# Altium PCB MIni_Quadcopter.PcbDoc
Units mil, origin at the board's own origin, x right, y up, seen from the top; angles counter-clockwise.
Board outline 2923.08 x 2923.08 mil, 2 copper layers (Top Layer, Bottom Layer); 50 components, 35 nets, 225 pads, 82 vias.
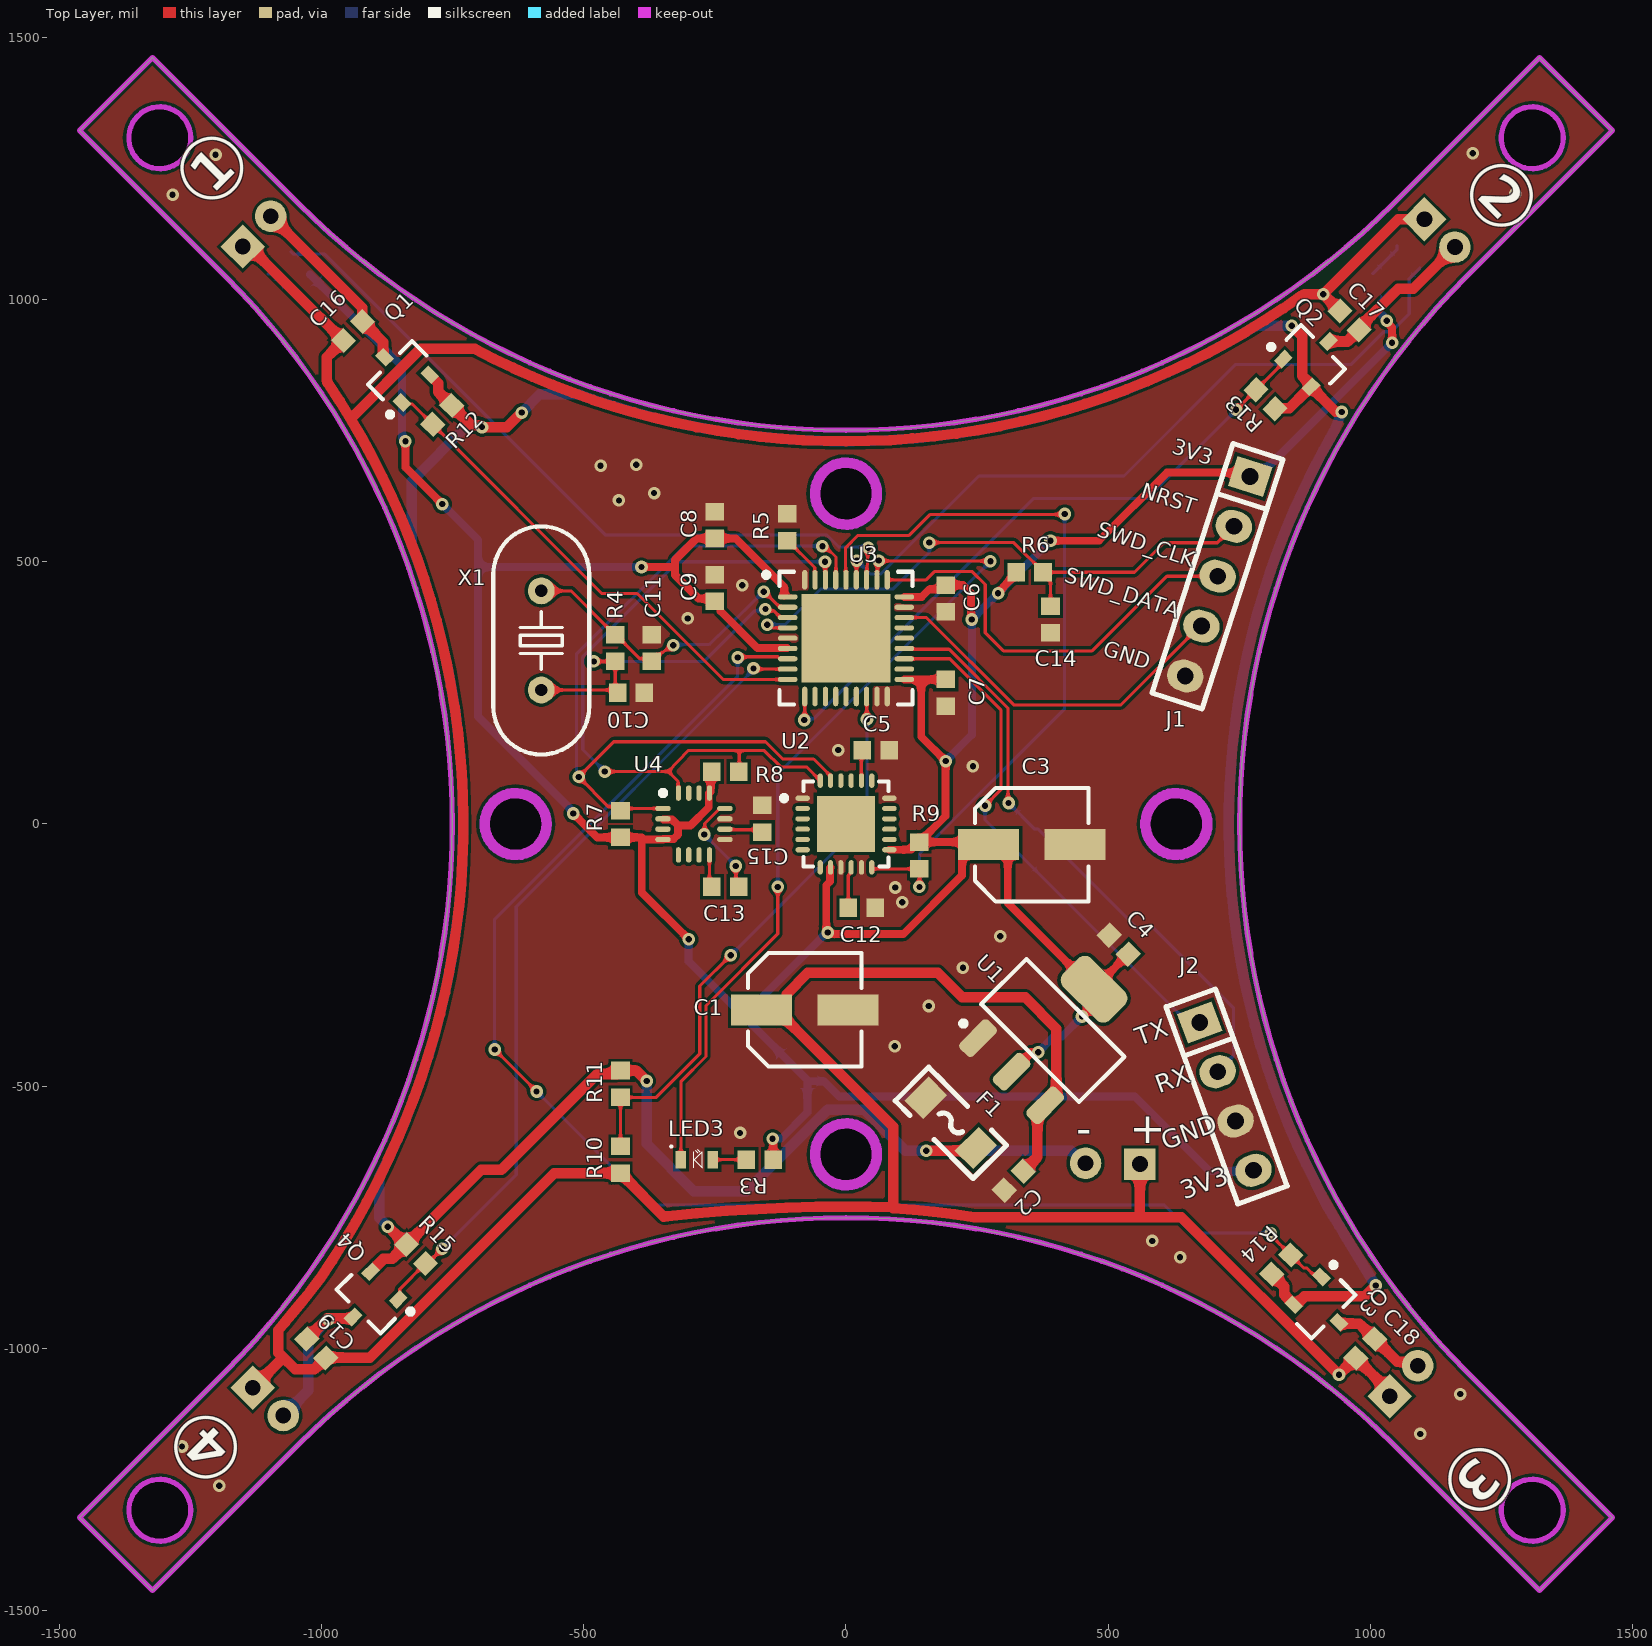
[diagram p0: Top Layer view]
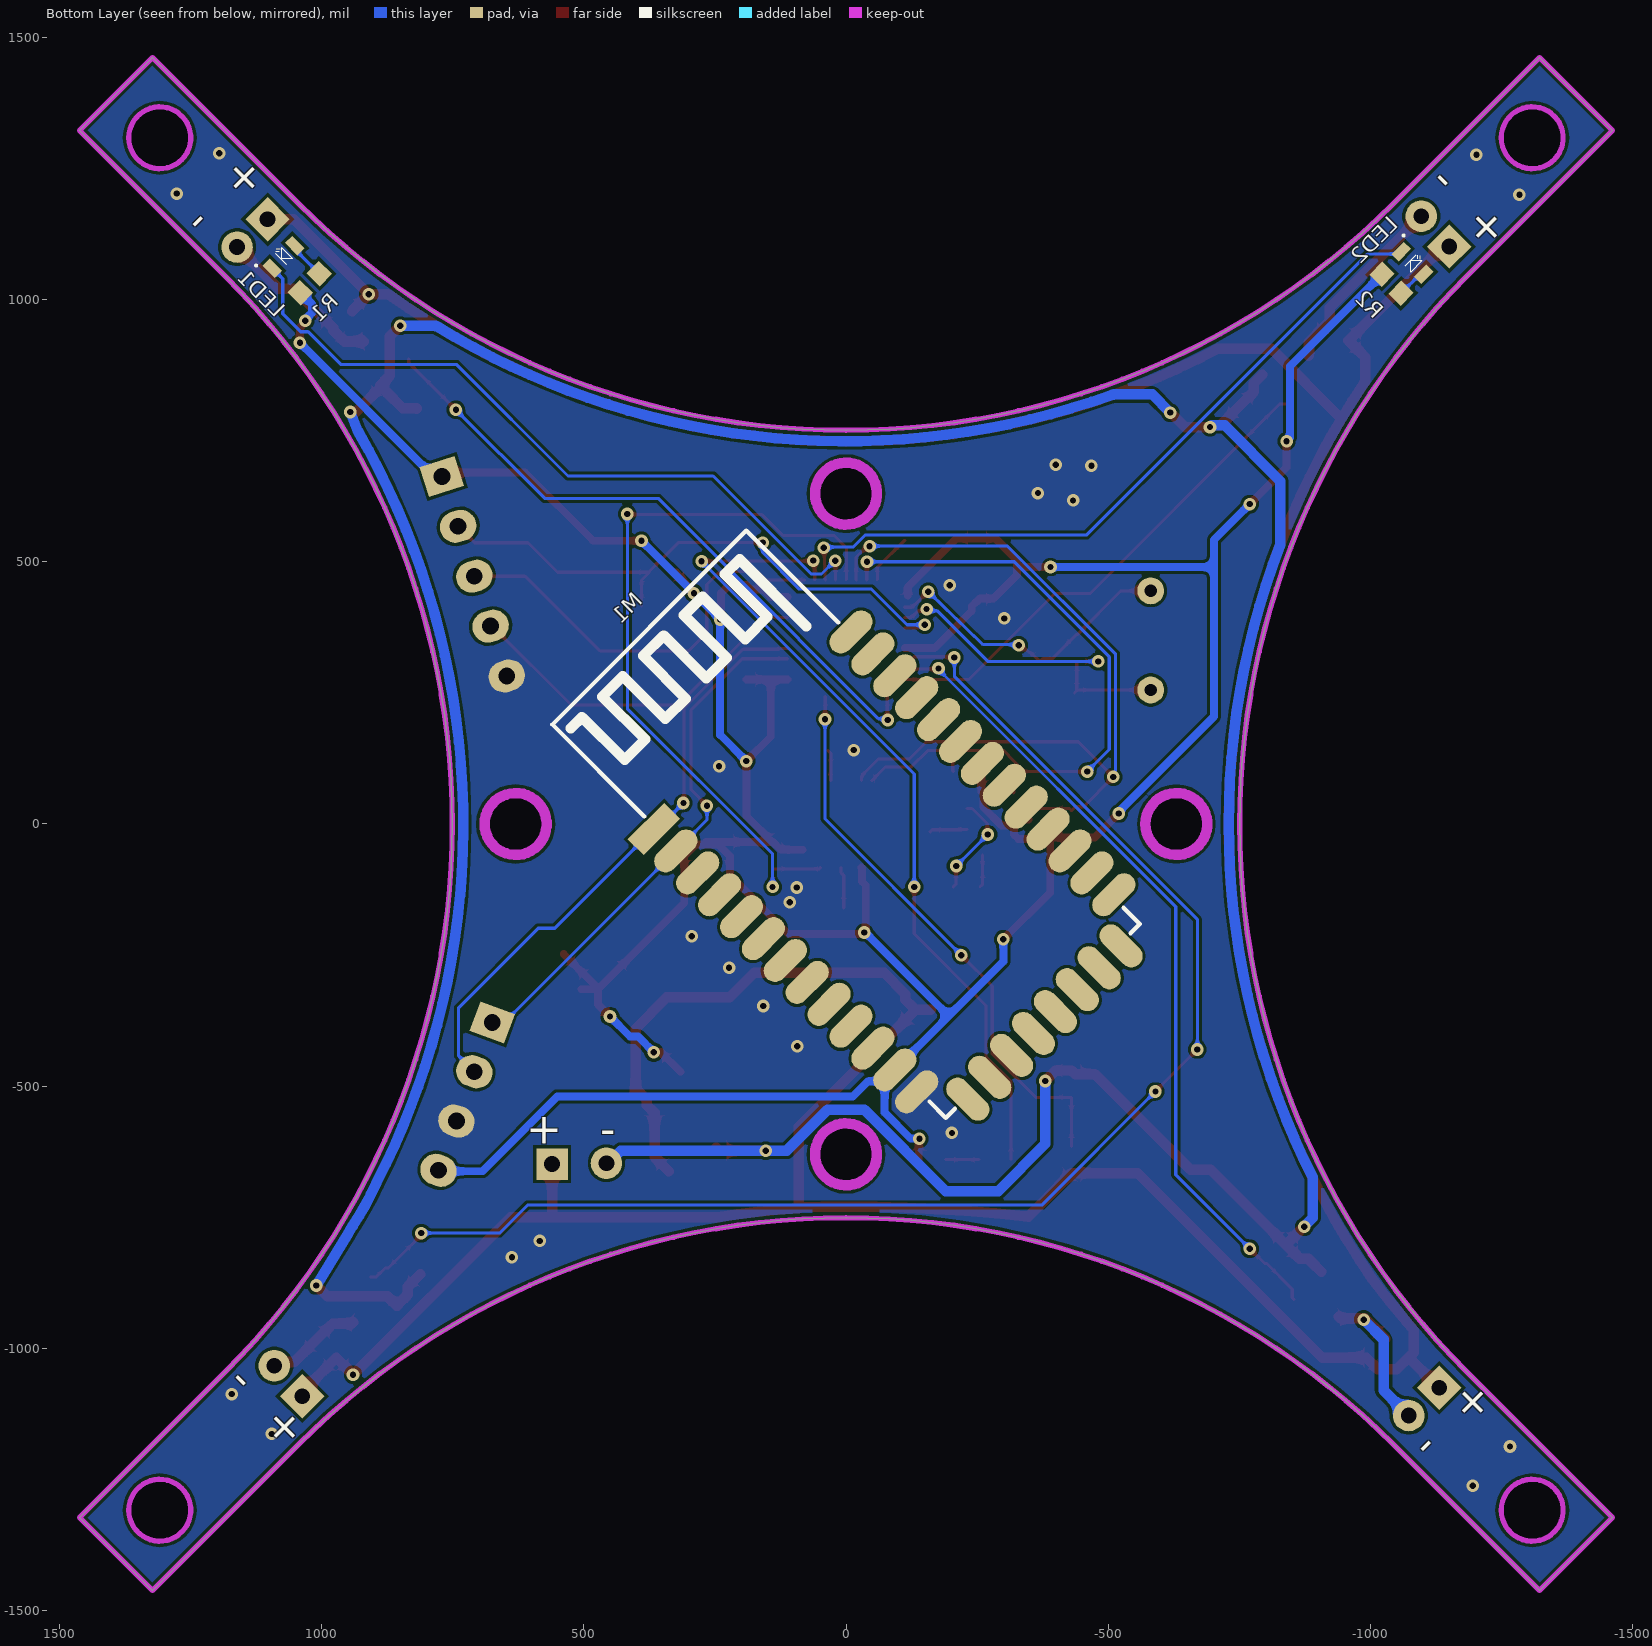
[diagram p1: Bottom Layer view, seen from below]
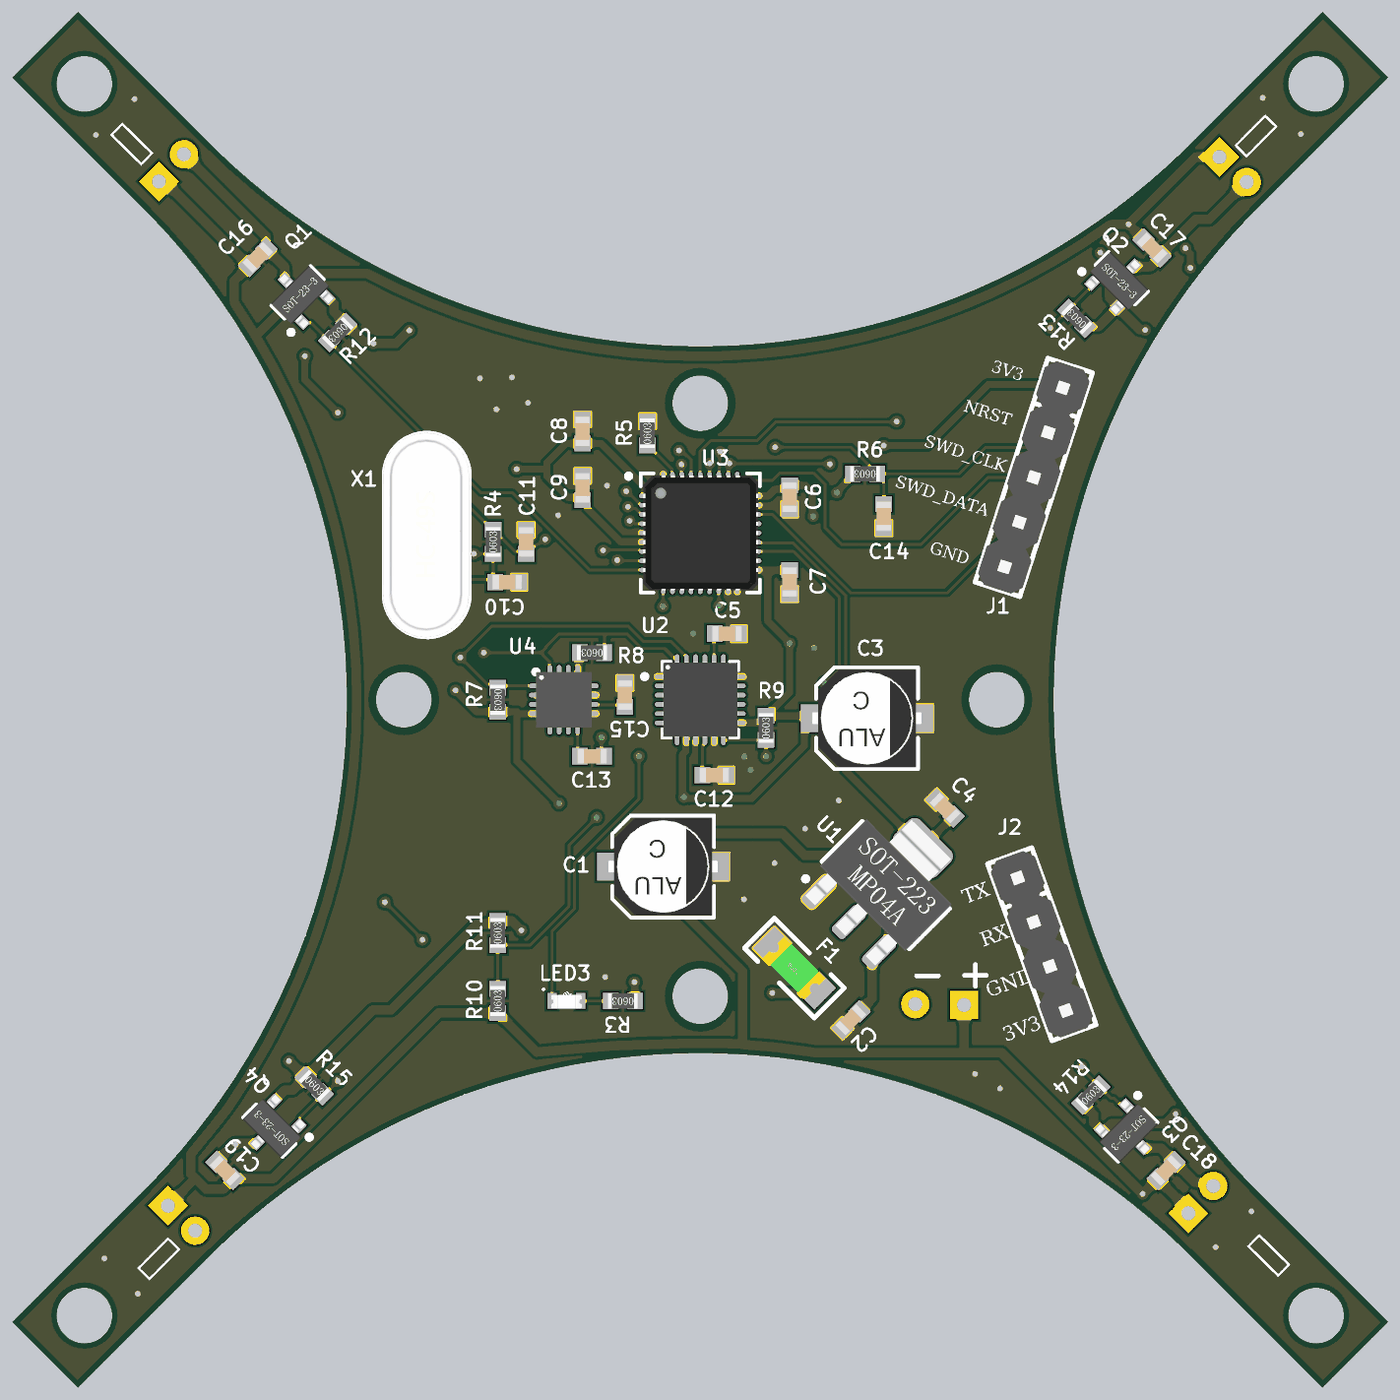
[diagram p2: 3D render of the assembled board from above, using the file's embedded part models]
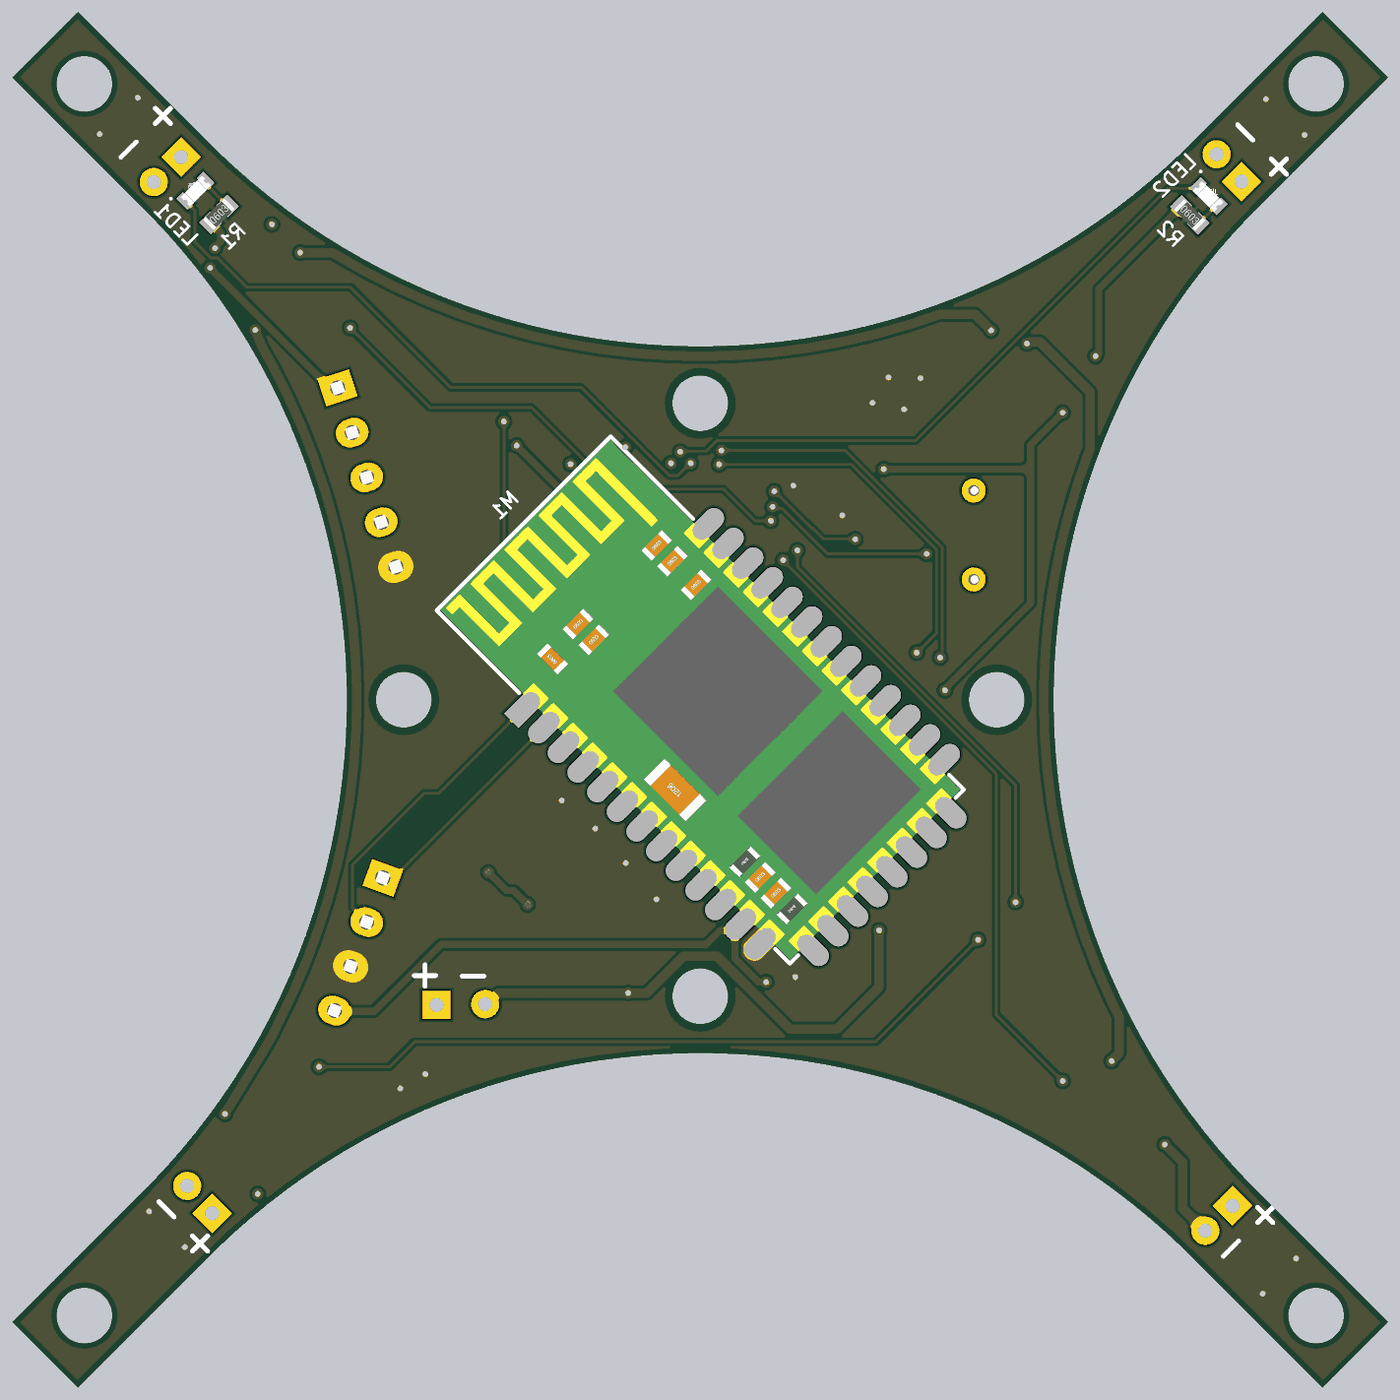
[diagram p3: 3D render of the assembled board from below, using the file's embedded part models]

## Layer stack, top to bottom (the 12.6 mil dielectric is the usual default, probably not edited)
Top Solder: solder mask 0.4, Solder Resist, Dk 3.5
Top Layer: signal copper 1.4
Dielectric 1: dielectric 12.6, FR-4, Dk 4.8
Bottom Layer: signal copper 1.4
Bottom Solder: solder mask 0.4, Solder Resist, Dk 3.5

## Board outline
-1461.54,-1322.35 -1322.35,-1461.54 -1043.96,-1183.15 cw(c0,-2227.11) 1043.96,-1183.15 1322.35,-1461.54 1461.54,-1322.35 1183.15,-1043.96 cw(c2227.11,0) 1183.15,1043.96 1461.54,1322.35 1322.35,1461.54 1043.96,1183.15 cw(c0,2227.11) -1043.96,1183.15 -1322.35,1461.54 -1461.54,1322.35 -1183.15,1043.96 cw(c-2227.11,0) -1183.15,-1043.96
cut-out: -1367.48,-1308.43 ccw(c-1308.43,-1308.43) -1308.43,-1367.48 ccw(c-1308.43,-1308.43) -1249.37,-1308.43 ccw(c-1308.43,-1308.43) -1308.43,-1249.37 ccw(c-1308.43,-1308.43)
cut-out: -59.06,-629.92 ccw(c0,-629.92) 0,-688.98 ccw(c0,-629.92) 59.06,-629.92 ccw(c0,-629.92) 0,-570.87 ccw(c0,-629.92)
cut-out: -688.98,0 ccw(c-629.92,0) -629.92,-59.06 ccw(c-629.92,0) -570.87,0 ccw(c-629.92,0) -629.92,59.06 ccw(c-629.92,0)
cut-out: 1249.37,-1308.43 ccw(c1308.43,-1308.43) 1308.43,-1367.48 ccw(c1308.43,-1308.43) 1367.48,-1308.43 ccw(c1308.43,-1308.43) 1308.43,-1249.37 ccw(c1308.43,-1308.43)
cut-out: 570.87,0 ccw(c629.92,0) 629.92,-59.06 ccw(c629.92,0) 688.98,0 ccw(c629.92,0) 629.92,59.06 ccw(c629.92,0)
cut-out: -59.06,629.92 ccw(c0,629.92) 0,570.87 ccw(c0,629.92) 59.06,629.92 ccw(c0,629.92) 0,688.98 ccw(c0,629.92)
cut-out: -1308.43,1249.37 cw(c-1308.43,1308.43) -1367.48,1308.43 cw(c-1308.43,1308.43) -1308.43,1367.48 cw(c-1308.43,1308.43) -1249.37,1308.43 cw(c-1308.43,1308.43)
cut-out: 1249.37,1308.43 ccw(c1308.43,1308.43) 1308.43,1249.37 ccw(c1308.43,1308.43) 1367.48,1308.43 ccw(c1308.43,1308.43) 1308.43,1367.48 ccw(c1308.43,1308.43)

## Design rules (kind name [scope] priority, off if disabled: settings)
Clearance [All] p1: gap=6 ignorepadtopadclearanceinfootprint=TRUE
PolygonConnect [All] p1: connectstyle=Direct reliefconductorwidth=10 reliefentries=4 polygonreliefangle="90 Angle" airgapwidth=10
RoutingVias [All] p1: holewidth=12 width=24 viastyle="Through Hole" minholewidth=12 minwidth=24 maxholewidth=12 maxwidth=24
SilkToSilkClearance [All] p1: silktosilkclearance=2
SilkToSolderMaskClearance [IsPad] p1: minsilkscreentomaskgap=2 clearancetoexposedcopper=TRUE
SolderMaskExpansion [All] p1: expansion=2.5 istentingtop=FALSE
Width MOTOR [InNetClass('MOTOR')] p1: maxlimit=60 minlimit=8 preferedwidth=20
Width PWR [InNetClass('PWR')] p2: maxlimit=60 minlimit=8 preferedwidth=15
Width [All] p3: maxlimit=6 minlimit=6 preferedwidth=6
28 further rules are at their usual default settings.

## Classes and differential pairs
net class MOTOR: MGND NetC16_1 NetC17_1 NetC18_1 NetC19_1 VCC
net class PWR: 3V3 GND

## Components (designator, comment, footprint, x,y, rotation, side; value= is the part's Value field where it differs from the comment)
C1 "47uF" Cap_SMD_5*5.4mm -78.74,-354.33 r0 top
C2 "0.1uF" C0603 320,-680 r45 top
C3 "47uF" Cap_SMD_5*5.4mm 354.33,-39.37 r0 top
C4 "0.1uF" C0603 520,-230 r315 top
C5 "2.2nF" C0603 56.64,140.46 r0 top
C6 "0.1uF" C0603 190,430 r90 top
C7 "0.1uF" C0603 190,250 r90 top
C8 "0.1uF" C0603 -250,570 r270 top
C9 "0.1uF" C0603 -250,450 r270 top
C10 "22P" C0603 -410,250 r0 top
C11 "22P" C0603 -370,335.59 r90 top
C12 "0.1uF" C0603 30,-160 r0 top
C13 "0.22uF" C0603 -230,-120 r0 top
C14 "1uF" C0603 390,390 r90 top
C15 "4.7uF" C0603 -160,10 r270 top
C16 "0.1uF" C0603 -940,940 r225 top
C17 "0.1uF" C0603 960,960 r135 top
C18 "0.1uF" C0603 990,-1000 r225 top
C19 "0.1uF" C0603 -1010,-1000 r315 top
F1 "MSMD200-8V 2A" "FU 1206" 200,-570 r135 top
J1 "Pin HDR1X5" "Pin HDR1X5/2.54mm-S" 770.46,662.65 r342 top
J2 "Pin HDR1X4" "Pin HDR1X4/2.54mm-S" 674.46,-378.47 r20 top
LED1 "LED" LED_0603 1072.48,1081.36 r135 bottom
LED2 "LED" LED_0603 -1080,1070 r225 bottom
LED3 "LED" LED_0603 -284.41,-640 r0 top
M1 "HC-05" HC-05 0.16,0 r135 bottom
Q1 "SI2302" SOT_23 -850,860 r135 top
Q2 "SI2302" SOT_23 890,890 r45 top
Q3 "SI2302" SOT_23 910,-920 r315 top
Q4 "SI2302" SOT_23 -910,-910 r225 top
R1 "470R" R0603 1022.48,1031.36 r135 bottom
R2 "470R" R0603 -1040,1030 r225 bottom
R3 "470R" R0603 -164.41,-640 r180 top
R4 "1M" R0603 -440,335.59 r90 top
R5 "470R" R0603 -112,566 r90 top
R6 "4.7K" R0603 350,480 r180 top
R7 "4.7K" R0603 -430,0 r270 top
R8 "4.7K" R0603 -230,100 r180 top
R9 "10K" R0603 140,-60 r90 top
R10 "10K" R0603 -430,-640 r90 top
R11 "10K" R0603 -430,-495.59 r90 top
R12 "10K" R0603 -770,780 r225 top
R13 "10K" R0603 800,810 r135 top
R14 "10K" R0603 830,-840 r45 top
R15 "10K" R0603 -820,-820 r315 top
U1 "AMS1117" SOT_223 394.33,-393.7 r45 top
U2 "MPU6050" QFN-24 0,0 r0 top
U3 "STM32F103T8U6" VFQFPN36_L 0,354.33 r0 top
U4 "HMC5883" LPCC-16-50P250X250X90-16N -290,0 r0 top
X1 "8MHZ" "OSC HC-49S" -581,350 r90 top

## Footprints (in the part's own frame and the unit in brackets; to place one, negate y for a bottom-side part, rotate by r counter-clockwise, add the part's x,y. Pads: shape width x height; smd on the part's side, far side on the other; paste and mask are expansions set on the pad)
C0603 [mm]
  rect 0.85x0.9 smd: 1(-0.65,0) 2(0.65,0)
  body extent -0.8,-0.4 0.8,0.4, height 0.8
Cap_SMD_5*5.4mm [mm]
  rect 2.95x1.5 smd: 1(-2.1,0) 2(2.1,0)
  silkscreen extent -2.75,-2.75 2.75,2.75, body extent -2.95,-2.65 2.95,2.65, height 5.41
"FU 1206" [mil] "贴片保险丝"
  rect 50x65 smd: 1(-67.5,0) 2(67.5,0)
  silkscreen extent -105,-45 105,45, body extent -63,-32 63,32, height 34
HC-05 [mm] "串口蓝牙模块"
  rect 2.5x1.1 smd: 1(-6.75,6.403)
  oval 2.5x1.1 smd: 2(-6.75,4.903) 3(-6.75,3.403) 4(-6.75,1.903) 5(-6.75,0.403) 6(-6.75,-1.097) 7(-6.75,-2.597) 8(-6.75,-4.097) 9(-6.75,-5.597) 10(-6.75,-7.097) 11(-6.75,-8.597) 12(-6.75,-10.097) 13(-6.75,-11.597) 22(6.75,-11.597) 23(6.75,-10.097) 24(6.75,-8.597) 25(6.75,-7.097) 26(6.75,-5.597) 27(6.75,-4.097) 28(6.75,-2.597) 29(6.75,-1.097) 30(6.75,0.403) 31(6.75,1.903) 32(6.75,3.403) 33(6.75,4.903) 34(6.75,6.403)
  oval 1.1x2.5 smd: 14(-5.25,-13.597) 15(-3.75,-13.597) 16(-2.25,-13.597) 17(-0.75,-13.597) 18(0.75,-13.597) 19(2.25,-13.597) 20(3.75,-13.597) 21(5.25,-13.597)
  silkscreen extent -6.65,-13.49 6.64,13.46, body extent -6.52,-13.37 6.52,13.35, height 2.46
LED_0603 [mm]
  rect 0.5x0.85 smd: 1(-0.775,0) 2(0.775,0)
  silkscreen extent -1.29,-0.38 0.25,0.69, body extent -0.82,-0.4 0.83,0.32, height 0.68
LPCC-16-50P250X250X90-16N [mm]
  oval 0.75x0.254 smd: 1(-1.5,0.75) 2(-1.5,0.25) 3(-1.5,-0.25) 4(-1.5,-0.75) 9(1.5,-0.75) 10(1.5,-0.25) 11(1.5,0.25) 12(1.5,0.75)
  oval 0.254x0.75 smd: 5(-0.75,-1.5) 6(-0.25,-1.5) 7(0.25,-1.5) 8(0.75,-1.5) 13(0.75,1.5) 14(0.25,1.5) 15(-0.25,1.5) 16(-0.75,1.5)
  silkscreen extent -1.62,1.38 -1.37,1.62, body extent -1.5,-1.5 1.5,1.5, height 0.9
"OSC HC-49S" [mm]
  round 1.3 hole 0.6: 1(-2.4,0) 2(2.4,0)
  silkscreen extent -5.52,-2.32 5.52,2.33, body extent -5.53,-2.29 5.53,2.36, height 4.13
"Pin HDR1X4/2.54mm-S" [mil]
  rect 70x60 hole 32: 1(0,0)
  oval 70x60 hole 32: 2(0,-100) 3(0,-200) 4(0,-300)
  silkscreen extent -50,-350 50,50, body extent -50,-350 50,50, height 336
"Pin HDR1X5/2.54mm-S" [mil]
  rect 70x60 hole 32: 1(0,0)
  oval 70x60 hole 32: 2(0,-100) 3(0,-200) 4(0,-300) 5(0,-400)
  silkscreen extent -50,-450 50,50, body extent -50,-450 50,50, height 336
QFN-24 [mm]
  oval 0.7x0.25 smd: 1(-2.1,1.25) 2(-2.1,0.75) 3(-2.1,0.25) 4(-2.1,-0.25) 5(-2.1,-0.75) 6(-2.1,-1.25) 13(2.1,-1.25) 14(2.1,-0.75) 15(2.1,-0.25) 16(2.1,0.25) 17(2.1,0.75) 18(2.1,1.25)
  oval 0.25x0.7 smd: 7(-1.25,-2.1) 8(-0.75,-2.1) 9(-0.25,-2.1) 10(0.25,-2.1) 11(0.75,-2.1) 12(1.25,-2.1) 19(1.25,2.1) 20(0.75,2.1) 21(0.25,2.1) 22(-0.25,2.1) 23(-0.75,2.1) 24(-1.25,2.1)
  rect 2.8x2.7 smd: ""(0,0)
  silkscreen extent -3.12,-2.05 2.05,2.05, body extent -2.02,-2.02 2.02,2.02, height 0.95
R0603 [mm]
  rect 0.85x0.9 smd: 1(-0.65,0) 2(0.65,0)
  body extent -0.8,-0.4 0.8,0.4, height 0.45
SOT_23 [mm]
  rect 0.75x0.55 smd: 1(-1.075,0.95) 2(-1.075,-0.95) 3(1.075,0)
  silkscreen extent -1.2,-1.5 0.7,1.9, body extent -1.4,-1.45 1.4,1.45, height 1.2
SOT_223 [mm] "SOT223, 4-Leads, Body 6.50x7.00mm (avg), Pitch 2.30mm, IPC High Density"
  rrect50% 1.95x0.9 smd: 1(-2.825,2.3) 2(-2.825,0) 3(-2.825,-2.3)
  rrect50% 1.95x3.2 smd: 4(2.825,0)
  silkscreen extent -2.95,-3.35 1.55,3.42, body extent -3.48,-3.25 3.48,3.25, height 1.7
VFQFPN36_L [mm] "QFN, 36-Leads, Body 6x6mm, Pitch 0.5mm, Thermal Pad 4.3x4.3mm, IPC High Density"
  oval 0.95x0.25 smd: 1(-2.825,2) 2(-2.825,1.5) 3(-2.825,1) 4(-2.825,0.5) 5(-2.825,0) 6(-2.825,-0.5) 7(-2.825,-1) 8(-2.825,-1.5) 9(-2.825,-2) 19(2.825,-2) 20(2.825,-1.5) 21(2.825,-1) 22(2.825,-0.5) 23(2.825,0) 24(2.825,0.5) 25(2.825,1) 26(2.825,1.5) 27(2.825,2)
  oval 0.25x0.95 smd: 10(-2,-2.825) 11(-1.5,-2.825) 12(-1,-2.825) 13(-0.5,-2.825) 14(0,-2.825) 15(0.5,-2.825) 16(1,-2.825) 17(1.5,-2.825) 18(2,-2.825) 28(2,2.825) 29(1.5,2.825) 30(1,2.825) 31(0.5,2.825) 32(0,2.825) 33(-0.5,2.825) 34(-1,2.825) 35(-1.5,2.825) 36(-2,2.825)
  rect 4.3x4.3 smd: 37(0,0)
  silkscreen extent -3.99,-3.21 3.22,3.21, body extent -3.08,-3.1 3.13,3.1, height 0.9

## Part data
C1 C3: library part Cap2, "极性电容"
C2 C4 C5 C6 C7 C8 C9 C10 C11 C12 C13 C14 C15 C16 C17 C18 C19: library part Cap1, "无极电容"
F1: library part FU, "贴片保险丝"
LED1 LED2 LED3: "发光二极管"
M1: "串口蓝牙模块"
Q1 Q2 Q3 Q4: "N沟道 20V/3A"
R1 R2 R3 R4 R5 R6 R7 R8 R9 R10 R11 R12 R13 R14 R15: library part Res, "普通电阻"
U1: "稳压电源芯片降压IC"
U2: "六轴传感器"
U4: "地磁传感器"
X1: library part XTAL-2P, "2脚无源脚晶振"

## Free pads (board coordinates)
  rect 60x60 hole 30 rot 135: 2(-1150,1101) 2(1037,-1091)
  rect 60x60 hole 30 rot 45: 2(-1131,-1075) 2(1103,1153)
  rect 60x60 hole 30: 2(560.49,-648.46)
  round 60 hole 30: 2(1161,1100) 3(-1097,1159) 3(-1073,-1128) 3(456.78,-646.77) 3(1090,-1033)

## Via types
v1: diameter 24, hole 12, Top Layer to Bottom Layer, tented both sides, 82 vias

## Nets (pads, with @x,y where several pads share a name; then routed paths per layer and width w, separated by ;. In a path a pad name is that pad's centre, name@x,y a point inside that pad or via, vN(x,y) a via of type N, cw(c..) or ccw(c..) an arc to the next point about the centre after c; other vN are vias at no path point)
3V3: C3.1 C4.2 C6.2 C7.2 C8.2 C9.2 J1.1 J2.4 M1.12 R1.1 R2.1 R3.1 R6.2 R7.2 R8.2 R9.2 U1.2 U1.4 U2.8 U2.13 U3.1 U3.6 U3.19 U3.27 U4.2 U4.4 U4.13 | length 8107.3
  Top Layer w15: v1(-840,730) -840,680 v1(-770,610) ; v1(-520,20) -474.41,-25.59 R7.2 -389.43,-25.59 ; v1(-390,490) -329.39,490 ; U4.4 -385.49,-29.53 -389.43,-25.59 ; U4.4@-347.87,-28.34 -328.34,-28.34 -320,-20 -320,-2.97 ; U4.2@-347.87,8.66 -331.63,8.66 -320,-2.97 ; v1(-300,-220) -389.43,-130.57 -389.43,-25.59 ; U4.13@-261.66,57.87 -261.66,32.03 -296.66,-2.97 -320,-2.97 ; U4.13 -258.03,61.5 -258.03,97.56 R8.2 ; v1(-140,-600) cw(c-142.85,-602.85) -138.82,-602.85 R3.1 ; U3.1@-117.77,435.65 -117.77,451.86 -210.32,544.41 C8.2 -284.98,544.41 -326.1,503.28 -326.1,474.89 -281.22,430 -255.59,430 C9.2 -249.02,424.41 -239.78,415.18 -239.78,406.4 -169.09,335.71 U3.6@-112.29,335.71 ; U2.8 -30.79,-83.94 -30.79,-109.96 -37.65,-116.81 -37.65,-203.85 v1(-34.57,-206.92) -31.49,-210 109.07,-210 221.08,-97.99 221.08,-61.4 243.11,-39.37 C3.1 ; U2.13 124.21,-49.21 139.02,-34.41 R9.2 R9.2@140.98,-34.41 ; U3.19 143.42,275.59 ; U3.27 144.46,433.07 158.78,447.4 181.8,447.4 C6.2 222.83,455.59 238.28,440.14 238.28,391.72 v1(240,390) ; C7.2 143.42,275.59 ; v1(290,440) 324.41,479.02 R6.2 ; U1.2 353.03,-435 v1(366.5,-435) ; v1(390,540) 482.07,540.04 612.03,670 763.12,670 J1.1 ; v1(450,-367) 472.98,-344.02 U1.4 ; U1.4@504.55,-315.06 U1.4 ; C4.2 472.98,-313.21 U1.4 ; J2.4@775.31,-658.63 J2.4 ; v1(1031.01,959.47) 1031.01,957.03 1041.24,946.8 v1(1041.24,917.52) ; R9.2@140.98,-34.41 266.69,-34.41 C3.1 ; R9.2@140.98,-34.41 150.22,-25.18 150.22,-24.19 190,15.59 v1(190,120) 143.42,166.58 143.42,275.59 ; C3.1 286.5,-39.37 308.53,-61.4 308.53,-150.61 U1.4
  Bottom Layer w15: R2.1 -846.52,872.71 -846.52,736.52 v1(-840,730) ; v1(-770,610) -701.77,541.77 -701.77,490 ; v1(-520,20) -520,22.44 -524.5,26.94 -524.5,27.68 -701.77,204.96 -701.77,490 ; v1(-390,490) -701.77,490 ; v1(-300,-220) -300,-262.02 -196.01,-366.01 ; v1(-140,-600) -123.6,-600 -73.69,-550.09 M1.12@-73.69,-488.49 ; v1(-34.57,-206.92) -36.92,-206.92 -196.01,-366.01 ; v1(190,120) 240,170 v1(240,390) v1(290,440) v1(390,540) ; v1(366.5,-435) 396.57,-404.93 412.07,-404.93 v1(450,-367) ; J1.1 786.37,662.65 v1(1041.24,917.52) ; J2.4 775.36,-662.09 693.02,-662.09 550.64,-519.72 -12.76,-519.72 -42.07,-490.41 -71.62,-490.41 M1.12 -196.01,-366.01 ; v1(1031.01,959.47) 1031.01,961.9 1018.5,974.41 1018.5,991.2 R1.1
GND: C1.2 C2.1 C3.2 C4.1 C5.2 C6.1 C7.1 C8.1 C9.1 C10.2 C11.2 C12.2 C14.1 C15.1 F1.2 J1.5 J2.3 M1.13 R5.2 U1.1 U2.1 U2.9 U2.11 U2.18 U3.5 U3.17 U3.18 U3.26 U3.36 U4.9 U4.11
  other v1: -1195,-1262 -1266,-1187 1095,-1163 1171,-1087 637,-826 584,-795 -202,-589 93,-424 158,-347 223,-274 294,-214 107,-149 94,-121 242,110 -15,141 -302,392 -198,455 -433,617 -366,631 -468,683 -400,685 -1284,1200 1276,1202 -1202,1276 1195,1279
INT_SENSOR: R9.1 U2.12 U3.32 | length 1459.3
  Top Layer w6: U3.32 -0.74,466.29 -0.74,526.73 22.97,550.43 120.43,550.43 160,590 416.1,590 v1(417.27,591.17) ; U2.12 49.21,-83.82 50.99,-85.59 R9.1 v1(140,-120)
  Bottom Layer w6: v1(140,-120) 140,-57.08 416.83,219.75 416.83,590.73 v1(417.27,591.17)
LED1: LED1.1 U3.31 | length 1402.1
  Top Layer w6: U3.31 19.97,465.84 19.97,501.92 v1(20.26,502.21)
  Bottom Layer w6: v1(20.26,502.21) 21.14,502.21 46.72,476.63 66.33,476.63 253.26,663.57 530.11,663.57 742.84,876.3 963.47,876.3 1025.64,938.47 1039.71,938.47 1073.93,972.7 1073.93,1039.67 LED1.1
LED2: LED2.1 U3.30 | length 1397.9
  Top Layer w6: U3.30 39.37,466.06 39.88,466.06 39.93,466.21 40.11,466.67 40.2,466.91 40.32,467.24 40.11,467.45 40.11,492.35 41.26,493.51 41.26,525.6 v1(42.54,526.88)
  Bottom Layer w6: LED2.1 -1053.55,1086.7 -994.22,1086.7 -458.41,550.9 -36.27,550.9 -13.39,528.03 41.39,528.03 v1(42.54,526.88)
LED3: LED3.1 U3.29 | length 1638.7
  Top Layer w6: LED3.1 -314.92,-491.23 -266.97,-443.28 -266.97,-346.54 -130,-209.58 v1(-130,-120) ; U3.29 59.53,466.02 59.53,477.94 59.79,478.21 59.79,499.79 v1(62.26,502.26) ; v1@61.08,500 62.63,501.54 274.69,501.54 v1(275.41,500.82)
  Bottom Layer w6: v1(-130,-120) -130,95.41 v1(275.41,500.82)
MGND: F1.1 pad.3@456.78,-646.77 Q1.2 Q2.2 Q3.2 Q4.2 R11.2 R12.1 R13.1 R14.1 R15.1 | length 7662.6
  Top Layer w20: Q4.2 -882,-829.1 -865.29,-829.1 R15.1 ; v1(-874.01,-767.71) -873.15,-767.71 -838.96,-801.9 R15.1 ; Q1.2 -777.78,840.67 -777.78,823.97 R12.1 -714.57,760.77 -699.06,760.77 -695.08,756.78 -646.87,756.78 -619.17,784.48 v1(-618.09,784.48) ; v1(-380,-490) -400,-470 R11.2 -436.73,-476.73 -474.61,-476.73 -656.9,-659.02 -695.21,-659.02 R15.1 ; v1(153.03,-623.03) 242.43,-623.03 F1.1 ; R14.1 835.75,-881.94 835.75,-897.47 853.63,-915.35 Q3.2 855.28,-918.17 856.44,-918.17 873.95,-900.67 989.33,-900.67 v1(1010,-880) ; R13.1 818.79,792.6 845.49,792.6 Q2.2 933.76,786.38 944.63,786.38 v1(945.4,785.62) ; v1(850,950) 869.65,930.35 869.65,854.7 888.04,836.31 Q2.2@888.04,835.14
  Bottom Layer w20: v1(-874.01,-767.71) -874.01,-766.63 -890,-750.64 -890,-674.01 ccw(c-2227.11,0) -729.73,-0.1 ccw(c-2227.11,0) -828.3,534.3 -828.3,653.52 -721.81,760 -697.22,760 v1(-694,756.78) ; v1(-618.09,784.48) -583.53,819.04 -511.61,819.04 cw(c-511.66,806.04) -507.3,818.28 ccw(c0,2227.11) 492.43,813.02 ccw(c0,2227.11) 778.7,948.13 cw(c785.41,937) 785.36,950 v1(850,950) ; v1(-380,-490) -380,-610 -290,-700 -190.36,-700 -35.23,-544.87 35.23,-544.87 113.4,-623.03 429.17,-623.03 452.9,-646.77 pad.3@456.78,-646.77 ; 790.96,-423.83 ccw(c1707.99,-153.18) 791.17,-424.51 ccw(c2227.11,0) 895.42,-684.65 cw(c883.85,-690.57) 895.67,-685.16 ccw(c1433.42,-440.22) 940.87,-766.67 cw(c930.06,-773.89) 941.17,-767.14 941.8,-768.19 ccw(c2227.11,0) 948.91,-779.96 v1(1010,-880) ; 790.95,-423.78 790.92,-423.67 cw(c2227.11,0) 930.79,749.47 v1(945.4,785.62)
NetC5_1: C5.1 U2.20 | length 59.6
  Top Layer w6: U2.20 29.17,83.04 29.17,134.76 C5.1@34.41,140
NetC10_1: C10.1 R4.1 U3.3 X1.1 | length 662
  Top Layer w6: X1.1 -441.1,255.51 C10.1@-440,254.41 ; v1(-481,310) R4.1 C10.1@-440,254.41 ; C10.1 C10.1@-440,254.41 ; v1(-153.68,409.77) -150.24,406.33 -137.63,406.33 -125,393.7 U3.3
  Bottom Layer w6: v1(-481,310) -270.33,310 -174,406.33 -157.13,406.33 v1(-153.68,409.77)
NetC11_1: C11.1 R4.2 U3.2 X1.2 | length 589.6
  Top Layer w6: X1.2 -524.29,444.49 -440.98,361.18 R4.2 -439.02,361.18 -393.2,315.37 -375.37,315.37 C11.1 -355.28,323.73 v1(-329.15,340.85) ; v1(-157.11,442.89) -155.55,442.89 -126.04,413.39 U3.2
  Bottom Layer w6: v1(-329.15,340.85) -327.99,342.01 -263.46,342.01 -261.03,342.01 -259.28,343.71 v1(-157.11,442.89)
NetC13_1: C13.1 U4.8 | length 63
  Top Layer w6: U4.8 -260.47,-115.12 C13.1
NetC13_2: C13.2 U4.12 | length 198.7
  Top Layer w6: v1(-270,-20) -269.35,-19.35 -269.35,1 -246.51,23.84 -246.22,23.84 -240.54,29.53 U4.12 ; v1(-210,-80) -210,-114.41 C13.2
  Bottom Layer w6: v1(-270,-20) v1(-210,-80)
NetC15_2: C15.2 U4.10 | length 73.3
  Top Layer w6: U4.10 -230.18,-10.61 -217.59,-10.61 -217.36,-10.84 -164.75,-10.84 C15.2
NetC16_1: C16.1 pad.3@-1097,1159 Q1.3 | length 359
  Top Layer w6: Q1.3@-882.71,892.71 Q1.3
  Top Layer w20: pad.3@-1097,1159 -922.6,984.6 -922.6,958.79 C16.1 -882.71,918.9 Q1.3@-882.71,892.71
NetC17_1: C17.1 pad.2@1161,1100 Q2.3 | length 320.5
  Top Layer w20: Q2.3 922.71,922.71 923.88,922.71 926.66,919.93 956.12,919.93 C17.1 978.1,946.15 1052.86,1020.92 1081.92,1020.92 pad.2@1161,1100
NetC18_1: C18.1 pad.3@1090,-1033 Q3.3 | length 184.5
  Top Layer w20: Q3.3 942.71,-952.71 978.9,-952.71 C18.1 1051.54,-1025.35 1082.35,-1025.35 pad.3@1090,-1033
NetC19_1: C19.1 pad.3@-1073,-1128 Q4.3 | length 324.2
  Top Layer w20: C19.1 -988.9,-942.71 -942.71,-942.71 Q4.3
  Bottom Layer w20: pad.3@-1073,-1128 -1024.89,-1079.89 -1024.89,-982.89 v1(-987,-945)
NetLED1_2: LED1.2 R1.2 | length 72.7
  Bottom Layer w6: R1.2 1050.91,1095.98 LED1.2
NetLED2_2: LED2.2 R2.2 | length 58.6
  Bottom Layer w6: LED2.2 -1094.62,1048.42 R2.2
NetLED3_2: LED3.2 R3.2 | length 63.9
  Top Layer w6: LED3.2 R3.2
NetR5_1: R5.1 U3.35 | length 97.4
  Top Layer w6: R5.1 -111.02,540.41 -59.79,489.18 -59.79,466.29 U3.35
NetR10_2: R10.2 R11.1 U3.16 | length 1092.4
  Top Layer w6: R10.2 R11.1 -361.84,-521.18 -278.97,-438.31 -278.97,-308.97 v1(-220,-250) ; U3.16 39.69,242.8 39.69,200.31 v1(40,200)
  Bottom Layer w6: v1(-220,-250) 40,10 v1(40,200)
NRST: C14.2 J1.2 R6.1 U3.4 | length 1137.4
  Top Layer w6: v1(-150,380) -145.13,380 -139.14,374.02 U3.4 ; v1(159,536.58) 319.99,536.58 375.59,480.98 R6.1 ; C14.2 390,464.61 375.59,479.02 R6.1 ; J1.2 708.17,536.15 606.37,536.15 550.21,480 R6.1
  Bottom Layer w6: v1(-150,380) -116.37,380 -48.61,447.76 89.07,447.76 159,517.69 v1(159,536.58)
PWM_DOWM: Q4.1 R15.2 U3.8 | length 1551.7
  Top Layer w6: Q4.1 -850.84,-903.74 -850.84,-887.03 R15.2 -798.1,-838.1 v1(-770,-810) ; v1(-176.45,296.59) -175.08,295.22 -111.28,295.22 U3.8
  Bottom Layer w6: v1(-770,-810) -628.77,-668.77 -628.77,-157.66 -176.45,294.66 v1(-176.45,296.59)
PWM_LEFT: Q3.1 R14.2 U3.7 | length 2795.1
  Top Layer w6: v1(-670,-430) v1(-590,-510) ; v1(-206.29,317.41) -204.93,318.77 -129.85,318.77 -126.04,314.96 U3.7 ; v1(810,-780) 810,-783.81 R14.2 872.77,-846.58 878.4,-846.58 895.45,-863.63 Q3.1
  Bottom Layer w6: v1(-670,-430) -670,-181.92 -206.66,281.42 -206.66,317.04 v1(-206.29,317.41) ; v1(-590,-510) -373.32,-726.68 607.29,-726.68 660.6,-780 v1(810,-780)
PWM_RIGHT: Q1.1 R12.2 U3.9 | length 954
  Top Layer w6: Q1.1 -843.74,800.84 -827.03,800.84 R12.2 -465.8,439.61 -398.22,439.61 -234.2,275.59 U3.9
PWM_UP: Q2.1 R13.2 U3.10 | length 1249
  Top Layer w6: U3.10 -78.68,243.05 -78.68,196.25 v1@-78.61,196.18 ; v1(743.81,790) R13.2 833.63,879.82 Q2.1
  Bottom Layer w6: v1(-79.45,198.38) -76.97,200.86 -61.84,200.86 242,504.7 358.09,620.79 574.6,620.79 v1(743.81,790)
REG: C12.1 U2.10 | length 79.6
  Top Layer w6: C12.1 4.41,-98.01 9.84,-92.58 U2.10
RX: J2.2 M1.1 U3.22 | length 1151.1
  Top Layer w6: U3.22 126.04,334.65 126.78,333.91 128.45,333.91 129.18,333.18 196.56,333.18 308.8,220.94 308.8,41.2 v1(310,40)
  Bottom Layer w6: v1(310,40) 359.66,-9.66 M1.1 555.38,-198.72 586.68,-198.72 739,-351.04 739,-441.22 708.66,-471.56 J2.2
SCL_SENSOR: R7.1 U2.23 U3.33 U4.1 | length 1601.4
  Top Layer w6: U4.1 -426.06,29.53 R7.1 -437.61,33.2 -453.2,33.2 v1(-509.77,89.77) -442.83,156.72 -153.54,156.72 -120.68,123.86 -61.65,123.86 -29.53,91.73 U2.23 ; v1(-45,529.58) -40.13,529.58 -28.14,517.59 -27.59,517.59 -19,509 -19,466.24 U3.33
  Bottom Layer w6: v1(-509.77,89.77) -513.21,93.21 -513.21,101.5 -514,102.29 -514,323.67 -307.67,530 -45.42,530 v1(-45,529.58)
SDA_SENSOR: R8.1 U2.24 U3.34 U4.16 | length 1348.9
  Top Layer w6: v1(-460,100) -338.67,100 ; U4.16 -320.29,59.82 -320.29,81.63 -338.67,100 ; R8.1 -203.51,100.89 -203.51,140 ; U2.24 -75.37,108.84 -124.75,108.84 -155.91,140 -203.51,140 ; v1(-40,500) -39.68,499.68 -39.68,465.87 U3.34 ; -338.67,100 -300.73,140 -203.51,140
  Bottom Layer w6: v1(-460,100) -502,142 -502,318.7 -320.7,500 v1(-40,500)
SWD_CLK: J1.3 U3.28 | length 812
  Top Layer w6: U3.28 80.52,465.55 152.78,465.55 168.56,481.32 240.71,481.32 265.4,456.63 265.4,364.6 300,330 469.29,330 611.73,472.44 J1.3
SWD_DATA: J1.4 U3.25 | length 697.8
  Top Layer w6: U3.25 153.08,393.7 319.69,227.09 524.3,227.09 674.55,377.34 J1.4
TX: J2.1 M1.2 U3.21 | length 1015.9
  Top Layer w6: U3.21 197.81,314.96 295.28,217.49 295.28,64.97 v1(265.15,34.85)
  Bottom Layer w6: v1(265.15,34.85) 265.15,7.84 324.41,-51.42 M1.2 651.62,-378.47 J2.1
VCC: C1.1 C2.2 C16.2 C17.2 C18.2 C19.2 pad.2@560.49,-648.46 pad.2@1037,-1091 pad.2@1103,1153 pad.2@-1131,-1075 pad.2@-1150,1101 R10.1 U1.3 | length 8722.2
  Top Layer w20: pad.2@-1150,1101 -1138.08,1101 -1048.83,1011.75 -958.99,921.9 C16.2 -990,890 -990,847.58 ccw(c-977,847.63) -987.8,840.39 cw(c-2227.11,0) -944.51,772.71 ; pad.2@-1131,-1075 -1074.5,-1018.5 -1074.5,-1015.5 ; C1.1 -132.87,-354.33 89.98,-577.18 89.98,-730.86 ccw(c0,-4302.4) -0.07,-729.73 ccw(c0,-3949.82) -340.93,-747.83 ccw(c0,-3949.82) -347.1,-748.49 -422.28,-673.31 -422.28,-672.32 -429.02,-665.59 R10.1 -556.09,-665.59 -907.9,-1017.4 -991.21,-1017.4 C19.2 -1013.81,-1040 -1050,-1040 -1074.5,-1015.5 ; C1.1@-127.79,-349.25 -113.35,-334.8 -113.35,-324.64 -72.59,-283.89 174.89,-283.89 221.75,-330.75 341.75,-330.75 401.09,-390.09 401.09,-504.09 379.72,-525.46 U1.3 365.1,-550.99 365.1,-634.9 C2.2 ; 89.88,-732.43 cw(c0,-2227.11) 244.79,-749.88 428,-749.88 560,-749.65 ; pad.2@560.49,-648.46 560.49,-749.16 560,-749.65 ; C17.2 v1(910,1010) ; pad.2@1037,-1091 1037,-1083.19 C18.2 v1(940,-1050) 639.52,-749.52 560,-749.65 ; pad.2@1103,1153 1053,1153 v1(910,1010) ; -1074.5,-1015.5 -1082.27,-1007.73 -1082.27,-965.14 ccw(c-2227.11,0) -1056.94,-934.26 ccw(c-2111.95,-32.26) -1056.8,-934.1 ccw(c-2111.95,-32.26) -1004.09,-868.5 ccw(c-2304.11,28.65) -823.72,-522.16 ccw(c-2227.11,0) -944.51,772.71 ; -944.51,772.71 -811.29,905.92 -708.29,905.92 ccw(c0,2241.49) 0,729.73 ccw(c0,2227.11) 868.91,1007.63 cw(c876.4,997) 876.35,1010 v1(910,1010)
pads on no net: M1.3 M1.4 M1.5 M1.6 M1.7 M1.8 M1.9 M1.10 M1.11 M1.14 M1.15 M1.16 M1.17 M1.18 M1.19 M1.20 M1.21 M1.22 M1.23 M1.24 M1.25 M1.26 M1.27 M1.28 M1.29 M1.30 M1.31 M1.32 M1.33 M1.34 U2. U2.2 U2.3 U2.4 U2.5 U2.6 U2.7 U2.14 U2.15 U2.16 U2.17 U2.19 U2.21 U2.22 U3.11 U3.12 U3.13 U3.14 U3.15 U3.20 U3.23 U3.24 U3.37 U4.3 U4.5 U4.6 U4.7 U4.14 U4.15

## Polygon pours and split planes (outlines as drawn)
GND on Top Layer "GND_L01_P003" (solid, remove dead copper, pour order 3): -1461.55,-1322.39 -1322.36,-1461.59 -1043.97,-1183.2 cw(c-0.01,-2227.15) 1043.94,-1183.2 1322.33,-1461.59 1461.53,-1322.39 1183.14,-1044 cw(c2227.09,-0.05) 1183.14,1043.91 1461.53,1322.3 1322.33,1461.49 1043.94,1183.11 cw(c-0.01,2227.06) -1043.97,1183.11 -1322.36,1461.49 -1461.55,1322.3 -1183.16,1043.91 cw(c-2227.12,-0.05) -1183.16,-1044
no net on Bottom Layer "NONET_L02_P002" (solid, remove dead copper, pour order 2): -1461.55,-1322.37 -1322.35,-1461.56 -1043.96,-1183.17 cw(c-0.01,-2227.13) 1043.95,-1183.17 1322.34,-1461.56 1461.53,-1322.37 1183.14,-1043.98 cw(c2227.1,-0.02) 1183.14,1043.93 1461.53,1322.32 1322.34,1461.52 1043.95,1183.13 cw(c-0.01,2227.08) -1043.96,1183.13 -1322.35,1461.52 -1461.55,1322.32 -1183.16,1043.93 cw(c-2227.11,-0.02) -1183.16,-1043.98
GND on Bottom Layer "GND_L02_P001" (solid, remove dead copper, pour order 1): -1461.54,-1322.35 -1322.35,-1461.54 -1043.96,-1183.15 cw(c0,-2227.11) 1043.96,-1183.15 1322.35,-1461.54 1461.54,-1322.35 1183.15,-1043.96 cw(c2227.11,0) 1183.15,1043.96 1461.54,1322.35 1322.35,1461.54 1043.96,1183.15 cw(c0,2227.11) -1043.96,1183.15 -1322.35,1461.54 -1461.54,1322.35 -1183.15,1043.96 cw(c-2227.11,0) -1183.15,-1043.96

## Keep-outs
Top Layer:
  circle w10: c-1308.43,-1308.45 r59.06
  circle w20: c-629.93,-0.02 r59.06
  circle w20: c-0.01,-629.94 r59.06
  circle w10: c-1308.43,1308.4 r59.06
  circle w20: c-0.01,629.9 r59.06
  circle w10: c1308.42,-1308.45 r59.06
  circle w20: c629.91,-0.02 r59.06
  circle w10: c1308.42,1308.4 r59.06
Keep-Out Layer:
  circle w10: c-1308.43,1308.43 r59.06
  circle w10: c-1308.43,-1308.43 r59.06
  circle w10: c1308.43,-1308.43 r59.06
  circle w10: c1308.43,1308.43 r59.06
  circle w20: c-629.92,0 r59.06
  circle w20: c0,-629.92 r59.06
  circle w20: c0,629.92 r59.06
  circle w20: c629.92,0 r59.06
  lines w10: -1461.54,-1322.35 -1322.35,-1461.54 -1043.96,-1183.15 cw(c0,-2227.11) 1043.96,-1183.15 1322.35,-1461.54 1461.54,-1322.35 1183.15,-1043.96 cw(c2227.11,0) 1183.15,1043.96 1461.54,1322.35 1322.35,1461.54 1043.96,1183.15 cw(c0,2227.11) -1043.96,1183.15 -1322.35,1461.54 -1461.54,1322.35 -1183.15,1043.96 cw(c-2227.11,0) -1183.15,-1043.96 -1461.54,-1322.35

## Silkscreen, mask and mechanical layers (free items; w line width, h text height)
Top Overlay:
  text "②" at 1131.18,1181.18 h200 r315
  text "①" at -1191.18,1131.18 h200 r45
  text "3V3" at 616.31,698.31 h50 r342
  text "NRST" at 557.33,614.22 h50 r342
  text "SWD_CLK" at 473.2,539.77 h50 r342
  text "SWD_DATA" at 411.74,453.7 h50 r342
  text "GND" at 484.99,313.41 h50 r342
  text "TX" at 563,-434 h60 r20
  text "RX" at 601,-525 h60 r20
  text "-" at 439,-609.99 h60
  text "+" at 541,-609 h60
  text "GND" at 612.85,-632.58 h60 r20
  text "3V3" at 648.85,-726.58 h60 r20
  text "③" at 1191.18,-1131.18 h200 r225
  text "④" at -1101.18,-1171.18 h200 r135
Bottom Overlay:
  text "-" at -1143.51,1252.89 h60 r225
  text "+" at 1189.06,1225.94 h60 r135
  text "+" at -1214.94,1180.06 h60 r225
  text "-" at 1261.89,1154.51 h60 r135
  text "+" at 541,-609.41 h60
  text "-" at 439,-610.4 h60
  text "-" at 1148.49,-1035.11 h60 r225
  text "+" at 1077.06,-1107.94 h60 r225
  text "+" at -1152.94,-1109.06 h60 r135
  text "-" at -1080.11,-1180.49 h60 r135
Mechanical 1:
  circle w10: c1308.43,-1308.43 r59.06

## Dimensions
-1322.35,1461.54 to 1461.54,-1322.35 on Drill Drawing
1322.35,1461.54 to -1461.54,-1322.35 on Drill Drawing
